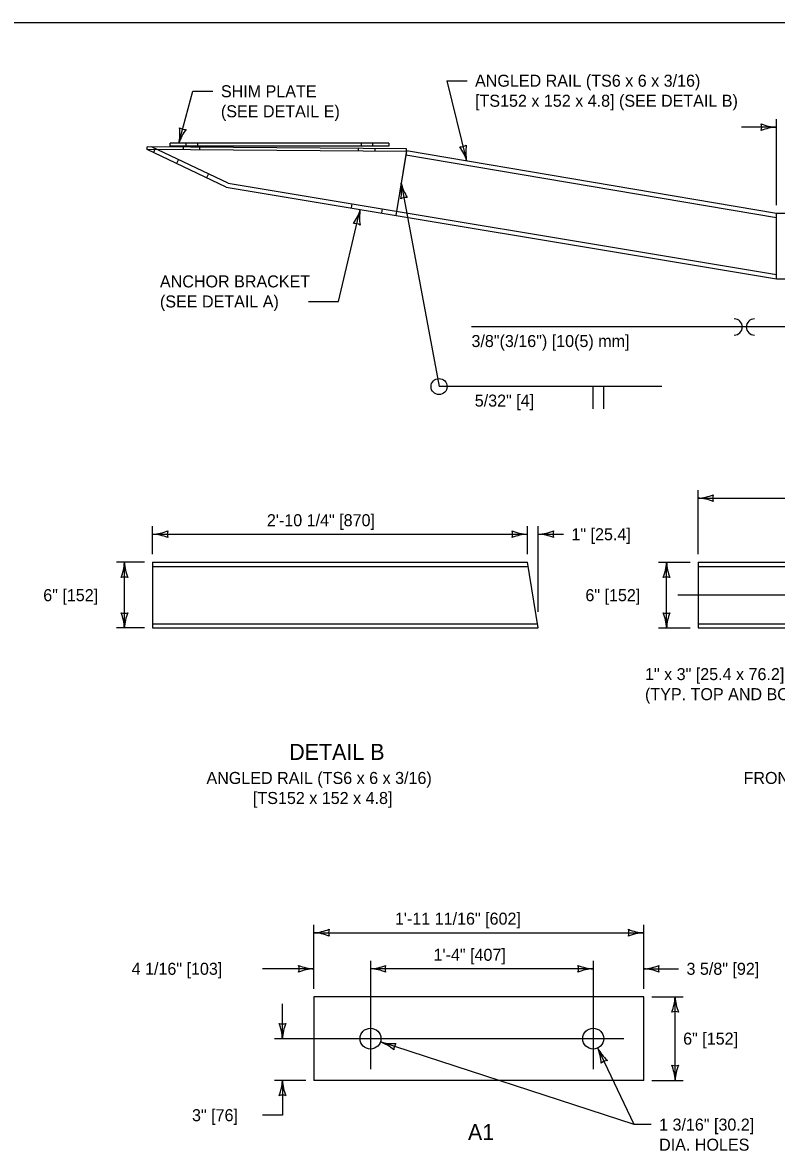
# Model space of a CAD drawing. Extents: x 49991.4 to 50021, y 49987.6 to 50011.4.
# Drawn here: x 50005.99 to 50009.75, y 49993.37 to 49999 of the extents above; entities that cross this region are included whole.
import ezdxf

# ---------------------------------------------------------------- set-up
doc = ezdxf.new("R2010")
doc.units = 0
for name, color, linetype in [('Level 1', 7, 'Continuous'), ('Level 2', 7, 'Continuous'), ('Level 3', 7, 'Continuous'), ('Level 4', 7, 'Continuous'), ('Level 5', 7, 'Continuous')]:
    doc.layers.add(name, color=color, linetype=linetype)

msp = doc.modelspace()

# ---------------------------------------------------------------- linework, layer by layer
at = {"layer": 'Level 1'}
for p, q in [((50007.814, 49998.3972), (50006.7223, 49998.3972)), ((50006.7223, 49998.3836), (50006.7223, 49998.3972)), ((50007.814, 49998.3972), (50007.814, 49998.3836)), ((50006.6084, 49998.3663), (50006.6085, 49998.38)), ((50007.9013, 49998.3559), (50006.6084, 49998.3663)), ((50007.0026, 49998.1786), (50006.6084, 49998.3663)), ((50007.9014, 49998.3695), (50006.6085, 49998.38)), ((50007.814, 49998.3836), (50006.7223, 49998.3836)), ((50007.9021, 49998.3607), (50007.8483, 49998.0377)), ((50007.9013, 49998.3559), (50007.8483, 49998.0377)), ((50007.9013, 49998.3559), (50007.9014, 49998.3695)), ((50007.9021, 49998.3607), (50009.7464, 49998.0488)), ((50007.0026, 49998.1786), (50009.7464, 49997.7213)), ((50009.7464, 49998.0488), (50015.4779, 49998.0488)), ((50009.7464, 49997.7213), (50009.7464, 49998.0488)), ((50009.7464, 49997.7213), (50013.7926, 49997.7213)), ((50006.6345, 49996.3075), (50008.5043, 49996.3075)), ((50006.6345, 49996.3075), (50006.6345, 49995.98)), ((50008.5589, 49995.98), (50008.5043, 49996.3075)), ((50009.3555, 49996.3075), (50009.3555, 49995.98)), ((50009.3555, 49996.3075), (50010.0174, 49996.3075)), ((50006.6345, 49995.98), (50008.5589, 49995.98)), ((50009.3555, 49995.98), (50010.0174, 49995.98)), ((50009.0844, 49994.1404), (50007.4395, 49994.1404)), ((50007.4395, 49994.1404), (50007.4395, 49993.7237)), ((50009.0844, 49993.7237), (50009.0844, 49994.1404)), ((50009.0844, 49993.7237), (50007.4395, 49993.7237))]:
    msp.add_line(p, q, dxfattribs=at)
msp.add_lwpolyline([(49999.3835, 49998.9992), (50016.7501, 49998.9992), (50016.7501, 49987.7988), (49999.3835, 49987.7988)], close=True, dxfattribs=at)
for centre in [(50007.7216, 49993.9321), (50008.8327, 49993.9321)]:
    msp.add_circle(centre, 0.0521, dxfattribs=at)
at = {"layer": 'Level 3'}
for p, q in [((50008.1032, 49998.7094), (50008.2032, 49998.7094)), ((50008.1032, 49998.7094), (50008.2013, 49998.3101)), ((50006.7662, 49998.3972), (50006.8358, 49998.6568)), ((50006.8358, 49998.6568), (50006.9358, 49998.6568)), ((50009.7464, 49998.0888), (50009.7464, 49998.517)), ((50009.7464, 49998.477), (50009.573, 49998.477)), ((50007.8751, 49998.1985), (50008.0637, 49997.184)), ((50007.4125, 49997.6084), (50007.5627, 49997.6084)), ((50009.1744, 49997.184), (50008.0637, 49997.184)), ((50008.831, 49997.184), (50008.831, 49997.0726)), ((50008.8845, 49997.184), (50008.8845, 49997.0726)), ((50009.3555, 49996.3475), (50009.3555, 49996.6675)), ((50009.3555, 49996.6275), (50010.8916, 49996.6275)), ((50006.6345, 49996.3475), (50006.6345, 49996.4875)), ((50008.5043, 49996.3475), (50008.5043, 49996.4875)), ((50008.5589, 49996.06), (50008.5589, 49996.4875)), ((50006.6345, 49996.4475), (50008.5043, 49996.4475)), ((50008.5589, 49996.4475), (50008.6841, 49996.4475)), ((50006.5945, 49996.3075), (50006.4545, 49996.3075)), ((50006.4945, 49995.98), (50006.4945, 49996.3075)), ((50009.1587, 49996.3075), (50009.3155, 49996.3075)), ((50009.1987, 49995.98), (50009.1987, 49996.3075)), ((50006.5945, 49995.98), (50006.4545, 49995.98)), ((50009.1587, 49995.98), (50009.3155, 49995.98)), ((50007.4395, 49994.1804), (50007.4395, 49994.5004)), ((50007.4395, 49994.4604), (50009.0844, 49994.4604)), ((50009.0844, 49994.1804), (50009.0844, 49994.5004)), ((50007.4395, 49994.2804), (50007.1827, 49994.2804)), ((50008.8327, 49994.2804), (50007.7212, 49994.2804)), ((50009.0844, 49994.2804), (50009.2579, 49994.2804)), ((50009.1244, 49994.1404), (50009.2812, 49994.1404)), ((50009.2412, 49993.7237), (50009.2412, 49994.1404)), ((50007.2827, 49993.9321), (50007.2827, 49994.1055)), ((50009.0361, 49993.5033), (50008.855, 49993.885)), ((50007.3995, 49993.7237), (50007.2427, 49993.7237)), ((50007.2827, 49993.7237), (50007.2827, 49993.5503)), ((50009.1244, 49993.7237), (50009.2812, 49993.7237)), ((50007.2827, 49993.5503), (50007.1827, 49993.5503))]:
    msp.add_line(p, q, dxfattribs=at)
for points in [[(50007.5627, 49997.6084), (50007.6709, 49998.0672)], [(50011.3246, 49998.0488), (50010.7894, 49997.4811), (50008.2254, 49997.4811)], [(50009.1212, 49993.5033), (50009.0361, 49993.5033), (50007.7711, 49993.9158)]]:
    msp.add_lwpolyline(points, dxfattribs=at)
msp.add_circle((50008.0637, 49997.184), 0.0401, dxfattribs=at)
for centre, radius, start, end in [((50006.5384, 49998.4464), 0.233, 347.8033, 7.0531), ((50006.9783, 49998.3308), 0.2223, 142.432, 162.6155), ((50006.7994, 49998.521), 0.0548, 237.1148, 272.8371), ((50009.7556, 49998.6991), 0.2223, 247.456, 267.6395), ((50009.6182, 49998.477), 0.0548, 342.1388, 17.8612), ((50009.7579, 49998.2443), 0.233, 92.8273, 112.0772), ((50008.1707, 49998.4346), 0.0548, 265.949, 301.6713), ((50007.9878, 49998.2482), 0.2223, 16.1706, 36.3541), ((50008.4301, 49998.3545), 0.233, 171.733, 190.9828), ((50007.655, 49998.1668), 0.2223, 347.9923, 8.1758), ((50008.1017, 49998.2523), 0.233, 193.3636, 212.6134), ((50007.8985, 49998.0724), 0.0548, 82.6751, 118.3974), ((50007.4568, 49998.1271), 0.2223, 324.186, 344.3695), ((50007.9, 49998.025), 0.233, 169.5573, 188.8071), ((50007.6414, 49997.9424), 0.0548, 58.8688, 94.5911), ((50009.5362, 49997.4811), 0.0401, 270, 90), ((50009.6364, 49997.4811), 0.0401, 90, 270), ((50009.344, 49996.8602), 0.233, 272.8273, 292.0772), ((50009.4837, 49996.6275), 0.0548, 162.1388, 197.8612), ((50009.3463, 49996.4053), 0.2223, 67.456, 87.6395), ((50006.623, 49996.6802), 0.233, 272.8273, 292.0772), ((50006.6254, 49996.2253), 0.2223, 67.456, 87.6395), ((50006.7627, 49996.4475), 0.0548, 162.1388, 197.8612), ((50008.5135, 49996.6696), 0.2223, 247.456, 267.6395), ((50008.3761, 49996.4475), 0.0548, 342.1388, 17.8612), ((50008.5158, 49996.2147), 0.233, 92.8273, 112.0772), ((50008.5497, 49996.6696), 0.2223, 272.3605, 292.544), ((50008.5474, 49996.2147), 0.233, 67.9228, 87.1727), ((50008.6871, 49996.4475), 0.0548, 162.1388, 197.8612), ((50006.2724, 49996.3166), 0.2223, 337.456, 357.6395), ((50006.7272, 49996.319), 0.233, 182.8273, 202.0772), ((50008.966, 49996.319), 0.233, 337.9228, 357.1727), ((50009.4208, 49996.3166), 0.2223, 182.3605, 202.544), ((50006.4945, 49996.1792), 0.0548, 72.1388, 107.8612), ((50009.1987, 49996.1792), 0.0548, 72.1388, 107.8612), ((50006.4945, 49996.1082), 0.0548, 252.1388, 287.8612), ((50006.2618, 49995.9685), 0.233, 2.8273, 22.0772), ((50006.7167, 49995.9708), 0.2223, 157.456, 177.6395), ((50008.9766, 49995.9708), 0.2223, 2.3605, 22.544), ((50009.1987, 49996.1082), 0.0548, 252.1388, 287.8612), ((50009.4314, 49995.9685), 0.233, 157.9228, 177.1727), ((50007.428, 49994.6931), 0.233, 272.8273, 292.0772), ((50007.4303, 49994.2383), 0.2223, 67.456, 87.6395), ((50007.5677, 49994.4604), 0.0548, 162.1388, 197.8612), ((50009.0936, 49994.6825), 0.2223, 247.456, 267.6395), ((50008.9562, 49994.4604), 0.0548, 342.1388, 17.8612), ((50009.0959, 49994.2277), 0.233, 92.8273, 112.0772), ((50007.4486, 49994.5025), 0.2223, 247.456, 267.6395), ((50007.3112, 49994.2804), 0.0548, 342.1388, 17.8612), ((50007.451, 49994.0477), 0.233, 92.8273, 112.0772), ((50007.7097, 49994.5131), 0.233, 272.8273, 292.0772), ((50007.712, 49994.0583), 0.2223, 67.456, 87.6395), ((50007.8494, 49994.2804), 0.0548, 162.1388, 197.8612), ((50008.8419, 49994.5025), 0.2223, 247.456, 267.6395), ((50008.7045, 49994.2804), 0.0548, 342.1388, 17.8612), ((50008.8442, 49994.0477), 0.233, 92.8273, 112.0772), ((50009.0753, 49994.5025), 0.2223, 272.3605, 292.544), ((50009.0729, 49994.0477), 0.233, 67.9228, 87.1727), ((50009.2126, 49994.2804), 0.0548, 162.1388, 197.8612), ((50009.0085, 49994.1519), 0.233, 337.9228, 357.1727), ((50009.4634, 49994.1496), 0.2223, 182.3605, 202.544), ((50009.2412, 49994.0122), 0.0548, 72.1388, 107.8612), ((50007.0605, 49993.9229), 0.2223, 2.3605, 22.544), ((50007.2827, 49994.0603), 0.0548, 252.1388, 287.8612), ((50007.5154, 49993.9206), 0.233, 157.9228, 177.1727), ((50007.8312, 49994.1298), 0.2223, 254.3015, 274.485), ((50007.688, 49993.6981), 0.233, 49.8638, 69.1137), ((50007.893, 49993.8761), 0.0548, 144.0798, 179.8022), ((50009.051, 49993.9899), 0.2223, 208.1488, 228.3323), ((50008.6405, 49993.7941), 0.233, 3.7111, 22.961), ((50008.9108, 49993.7696), 0.0548, 97.9271, 133.6495), ((50009.0191, 49993.7146), 0.2223, 2.3605, 22.544), ((50009.2412, 49993.852), 0.0548, 252.1388, 287.8612), ((50009.4739, 49993.7123), 0.233, 157.9228, 177.1727), ((50007.05, 49993.7352), 0.233, 337.9228, 357.1727), ((50007.5048, 49993.7329), 0.2223, 182.3605, 202.544), ((50007.2827, 49993.5955), 0.0548, 72.1388, 107.8612)]:
    msp.add_arc(centre, radius, start, end, dxfattribs=at)
at = {"layer": 'Level 4'}
for p, q in [((50006.8029, 49998.3836), (50006.8029, 49998.3972)), ((50006.86, 49998.3836), (50006.86, 49998.3972)), ((50007.6762, 49998.3836), (50007.6762, 49998.3972)), ((50007.7333, 49998.3836), (50007.7333, 49998.3972)), ((50007.0117, 49998.1981), (50006.6301, 49998.3798)), ((50006.6482, 49998.3712), (50006.639, 49998.3518)), ((50006.7892, 49998.3649), (50006.7893, 49998.3785)), ((50006.8711, 49998.3642), (50006.8712, 49998.3778)), ((50007.6625, 49998.3578), (50007.6626, 49998.3715)), ((50007.7444, 49998.3572), (50007.7445, 49998.3708)), ((50007.8986, 49998.3395), (50009.7464, 49998.027)), ((50006.7638, 49998.3161), (50006.7545, 49998.2967)), ((50006.9133, 49998.2449), (50006.9041, 49998.2255)), ((50007.0117, 49998.1981), (50009.7464, 49997.7431)), ((50007.6295, 49998.0953), (50007.6261, 49998.0747)), ((50007.7794, 49998.0704), (50007.776, 49998.0497)), ((50006.6345, 49996.286), (50008.5079, 49996.286)), ((50009.3555, 49996.286), (50010.0174, 49996.286)), ((50006.6345, 49996.0015), (50008.5553, 49996.0015)), ((50009.3555, 49996.0015), (50010.0174, 49996.0015))]:
    msp.add_line(p, q, dxfattribs=at)
at = {"layer": 'Level 5'}
for p, q in [((50010.0174, 49996.1437), (50009.2555, 49996.1437)), ((50007.7212, 49994.3204), (50007.7212, 49993.78)), ((50008.8327, 49994.3204), (50008.8327, 49993.78)), ((50007.2427, 49993.9321), (50008.9848, 49993.9321))]:
    msp.add_line(p, q, dxfattribs=at)

# ---------------------------------------------------------------- texts
at = {"layer": 'Level 2'}
for s, height, p in [('ANGLED RAIL (TS6 x 6 x 3/16)', 0.06, (50008.2432, 49998.6794)), ('SHIM PLATE', 0.06, (50006.9758, 49998.6268)), ('[TS152 x 152 x 4.8] (SEE DETAIL B)', 0.06, (50008.2432, 49998.5794)), ('(SEE DETAIL E)', 0.06, (50006.9758, 49998.5268)), ('2\'-10 1/4" [870]', 0.06, (50007.2052, 49996.4875)), ('1" [25.4]', 0.06, (50008.7241, 49996.4175)), ('6" [152]', 0.06, (50006.0896, 49996.1137)), ('6" [152]', 0.06, (50008.7937, 49996.1137)), ('1" x 3" [25.4 x 76.2] SLOTS ', 0.06, (50009.091, 49995.72)), ('(TYP. TOP AND BOTTOM)', 0.06, (50009.091, 49995.62)), ('DETAIL B', 0.08, (50007.3163, 49995.3221)), ('ANGLED RAIL (TS6 x 6 x 3/16) ', 0.06, (50006.9037, 49995.2021)), ('FRONT RAIL (TS6 x 6 x 3/16) ', 0.06, (50009.5825, 49995.2021)), ('[TS152 x 152 x 4.8]', 0.06, (50007.1355, 49995.1021)), ('1\'-11 11/16" [602]', 0.06, (50007.8438, 49994.5004)), ('1\'-4" [407]', 0.06, (50008.0363, 49994.3204)), ('3 5/8" [92]', 0.06, (50009.2979, 49994.2504)), ('A1', 0.08, (50008.2079, 49993.4258))]:
    msp.add_text(s, height=height, dxfattribs=at).set_placement(p)
for s, p in [('ANCHOR BRACKET', (50006.6717, 49997.6784)), ('(SEE DETAIL A)', (50006.6717, 49997.5784)), ('3/8"(3/16") [10(5) mm]', (50008.2254, 49997.3811)), (' 5/32" [4]', (50008.2196, 49997.084)), ('4 1/16" [103]', (50006.5304, 49994.2504)), ('6" [152]', (50009.2812, 49993.9021)), ('3" [76]', (50006.8316, 49993.5203)), ('1 3/16" [30.2] ', (50009.1612, 49993.4733)), ('DIA. HOLES', (50009.1612, 49993.3733))]:
    msp.add_text(s, height=0.06, rotation=360, dxfattribs=at).set_placement(p)

doc.saveas('drawing.dxf')
